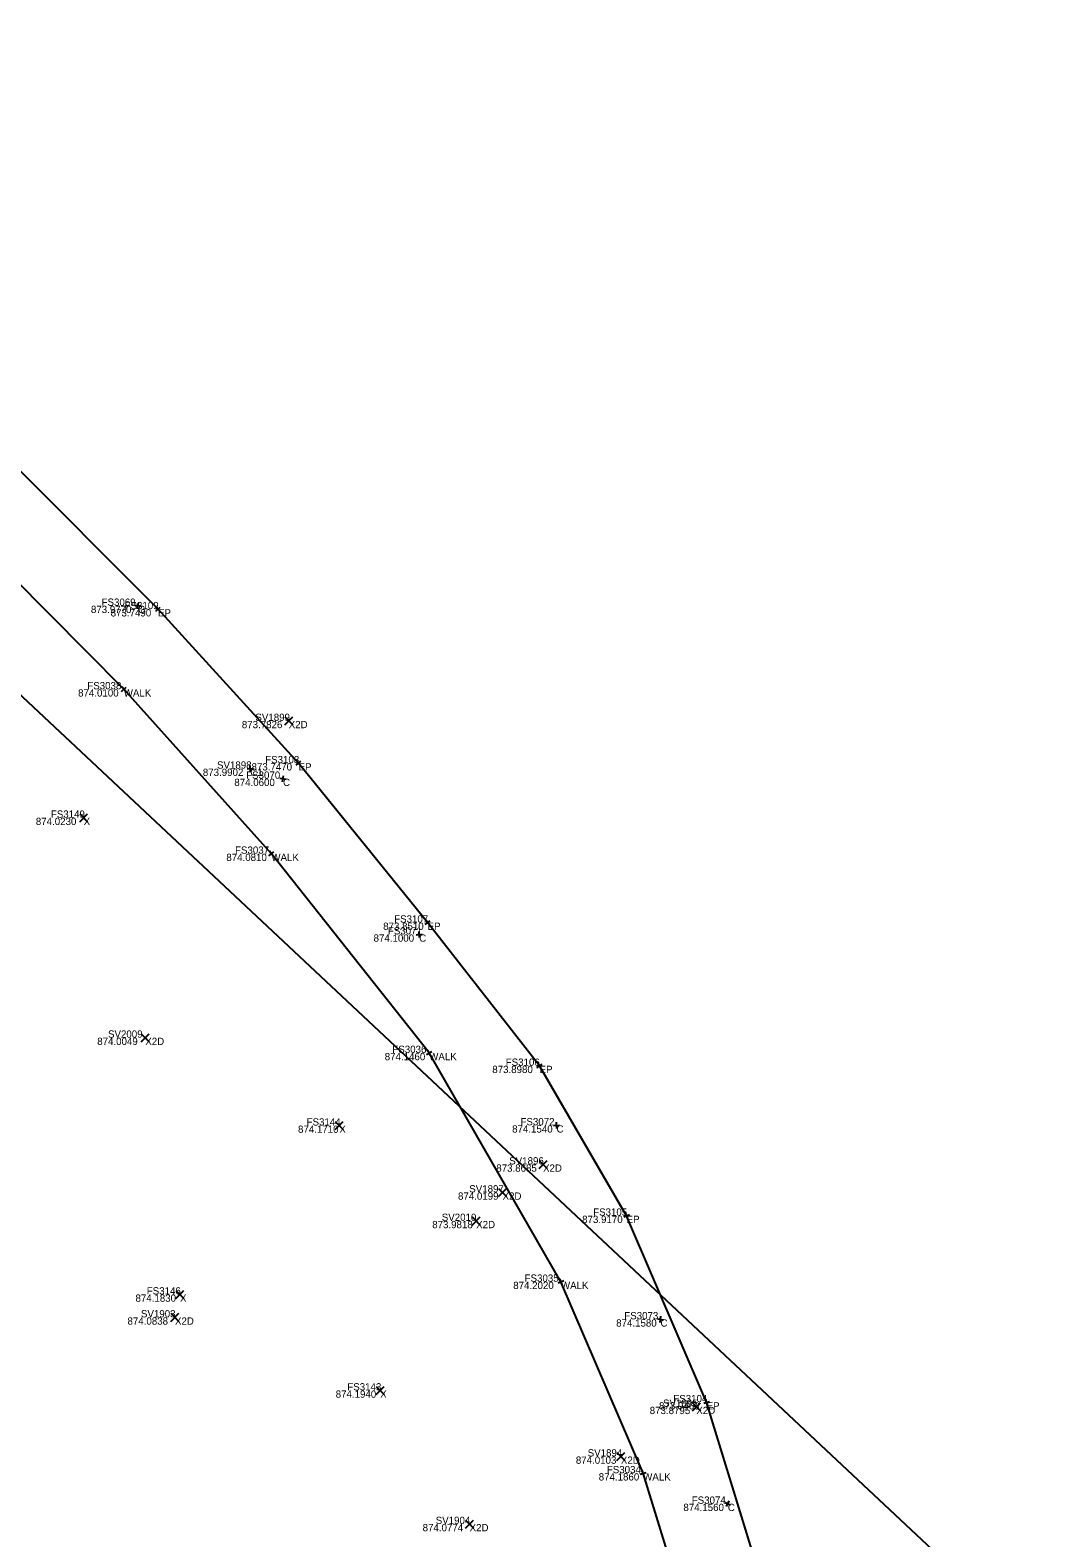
# Model space of a CAD drawing. Extents: x 1479481 to 1575806, y 316056 to 379927.
# Drawn here: x 1480137.43 to 1480145.75, y 379421.16 to 379433.6 of the extents above; entities that cross this region are included whole.
import ezdxf

# ---------------------------------------------------------------- set-up
doc = ezdxf.new("R2010")
doc.units = 0
for name, color, linetype in [('PV_X_Curb', 7, 'Continuous'), ('PV_X_Walk', 7, 'Continuous'), ('SV_X_Random_Point', 7, 'Continuous'), ('SV_X_Shot_Marker', 7, 'Continuous'), ('SV_X_Text_Comment', 7, 'Continuous'), ('SV_X_Text_Elevation', 7, 'Continuous'), ('SV_X_Text_Name', 7, 'Continuous'), ('UT_X_Water', 7, 'Continuous')]:
    doc.layers.add(name, color=color, linetype=linetype)

msp = doc.modelspace()

# ---------------------------------------------------------------- linework, layer by layer
at = {"layer": 'PV_X_Curb'}
for points in [[(1480144.119, 379408.692), (1480144.24, 379410.484), (1480144.247, 379412.184), (1480144.276, 379413.727), (1480144.183, 379415.462), (1480143.996, 379417.344), (1480143.813, 379419.16), (1480143.496, 379420.71), (1480143.015, 379422.278), (1480142.354, 379423.817), (1480141.636, 379425.054), (1480140.711, 379426.236), (1480139.646, 379427.551), (1480138.485, 379428.822), (1480137.236, 379430.074), (1480137.133, 379430.292), (1480135.667, 379431.559), (1480135.19, 379432.332), (1480118.45, 379448.16)], [(1480143.467, 379408.427), (1480143.491, 379410.102), (1480143.626, 379411.891), (1480143.667, 379412.715), (1480143.643, 379414.145), (1480143.592, 379415.709), (1480143.406, 379417.136), (1480143.175, 379418.964), (1480142.832, 379420.583), (1480142.491, 379421.692), (1480141.812, 379423.272), (1480140.724, 379425.16), (1480139.421, 379426.804), (1480138.202, 379428.161), (1480136.669, 379429.706), (1480137.114, 379430.095), (1480136.349, 379430.778), (1480135, 379431.897), (1480118.039, 379447.914)]]:
    msp.add_lwpolyline(points, dxfattribs=at)
at = {"layer": 'PV_X_Walk'}
msp.add_lwpolyline([(1480143.467, 379408.427), (1480143.491, 379410.102), (1480143.626, 379411.891), (1480143.667, 379412.715), (1480143.643, 379414.145), (1480143.592, 379415.709), (1480143.406, 379417.136), (1480143.175, 379418.964), (1480142.832, 379420.583), (1480142.491, 379421.692), (1480141.812, 379423.272), (1480140.724, 379425.16), (1480139.421, 379426.804), (1480138.202, 379428.161), (1480136.669, 379429.706), (1480135.545, 379428.421), (1480134.397, 379429.433)], dxfattribs=at)
at = {"layer": 'SV_X_Random_Point'}
for p, q in [((1480139.531, 379427.867), (1480139.597, 379427.933)), ((1480139.531, 379427.933), (1480139.597, 379427.867)), ((1480137.838, 379427.068), (1480137.904, 379427.134)), ((1480137.838, 379427.134), (1480137.904, 379427.068)), ((1480138.347, 379425.252), (1480138.413, 379425.319)), ((1480138.347, 379425.319), (1480138.413, 379425.252)), ((1480139.949, 379424.528), (1480140.015, 379424.594)), ((1480139.949, 379424.594), (1480140.015, 379424.528)), ((1480141.631, 379424.207), (1480141.697, 379424.273)), ((1480141.631, 379424.273), (1480141.697, 379424.207)), ((1480141.297, 379423.975), (1480141.363, 379424.042)), ((1480141.297, 379424.042), (1480141.363, 379423.975)), ((1480141.079, 379423.74), (1480141.145, 379423.807)), ((1480141.079, 379423.807), (1480141.145, 379423.74)), ((1480138.633, 379423.134), (1480138.699, 379423.2)), ((1480138.633, 379423.2), (1480138.699, 379423.134)), ((1480138.592, 379422.945), (1480138.658, 379423.012)), ((1480138.592, 379423.012), (1480138.658, 379422.945)), ((1480140.286, 379422.342), (1480140.352, 379422.408)), ((1480140.286, 379422.408), (1480140.352, 379422.342)), ((1480142.897, 379422.206), (1480142.963, 379422.273)), ((1480142.897, 379422.273), (1480142.963, 379422.206)), ((1480142.274, 379421.797), (1480142.34, 379421.863)), ((1480142.274, 379421.863), (1480142.34, 379421.797)), ((1480141.025, 379421.239), (1480141.091, 379421.306)), ((1480141.025, 379421.306), (1480141.091, 379421.239))]:
    msp.add_line(p, q, dxfattribs=at)
at = {"layer": 'SV_X_Shot_Marker'}
for p, q in [((1480138.295, 379428.854), (1480138.345, 379428.846)), ((1480138.316, 379428.825), (1480138.324, 379428.875)), ((1480138.32, 379428.85), (1480138.32, 379428.85)), ((1480138.467, 379428.805), (1480138.503, 379428.839)), ((1480138.502, 379428.804), (1480138.468, 379428.84)), ((1480138.485, 379428.822), (1480138.485, 379428.822)), ((1480138.183, 379428.144), (1480138.221, 379428.178)), ((1480138.219, 379428.142), (1480138.185, 379428.18)), ((1480138.202, 379428.161), (1480138.202, 379428.161)), ((1480139.222, 379427.504), (1480139.272, 379427.508)), ((1480139.249, 379427.481), (1480139.245, 379427.531)), ((1480139.247, 379427.506), (1480139.247, 379427.506)), ((1480139.627, 379427.535), (1480139.665, 379427.567)), ((1480139.662, 379427.532), (1480139.63, 379427.57)), ((1480139.646, 379427.551), (1480139.646, 379427.551)), ((1480139.492, 379427.427), (1480139.542, 379427.419)), ((1480139.513, 379427.398), (1480139.521, 379427.448)), ((1480139.517, 379427.423), (1480139.517, 379427.423)), ((1480139.401, 379426.788), (1480139.441, 379426.82)), ((1480139.437, 379426.784), (1480139.405, 379426.824)), ((1480139.421, 379426.804), (1480139.421, 379426.804)), ((1480140.691, 379426.221), (1480140.731, 379426.251)), ((1480140.726, 379426.216), (1480140.696, 379426.256)), ((1480140.711, 379426.236), (1480140.711, 379426.236)), ((1480140.617, 379426.136), (1480140.667, 379426.14)), ((1480140.644, 379426.113), (1480140.64, 379426.163)), ((1480140.642, 379426.138), (1480140.642, 379426.138)), ((1480140.702, 379425.148), (1480140.746, 379425.172)), ((1480140.736, 379425.138), (1480140.712, 379425.182)), ((1480140.724, 379425.16), (1480140.724, 379425.16)), ((1480141.614, 379425.041), (1480141.658, 379425.067)), ((1480141.649, 379425.032), (1480141.623, 379425.076)), ((1480141.636, 379425.054), (1480141.636, 379425.054)), ((1480141.751, 379424.562), (1480141.801, 379424.564)), ((1480141.777, 379424.538), (1480141.775, 379424.588)), ((1480141.776, 379424.563), (1480141.776, 379424.563)), ((1480142.331, 379423.807), (1480142.377, 379423.827)), ((1480142.364, 379423.794), (1480142.344, 379423.84)), ((1480142.354, 379423.817), (1480142.354, 379423.817)), ((1480141.789, 379423.262), (1480141.835, 379423.282)), ((1480141.822, 379423.249), (1480141.802, 379423.295)), ((1480141.812, 379423.272), (1480141.812, 379423.272)), ((1480142.631, 379422.937), (1480142.637, 379422.987)), ((1480142.609, 379422.965), (1480142.659, 379422.959)), ((1480142.634, 379422.962), (1480142.634, 379422.962)), ((1480142.991, 379422.271), (1480143.039, 379422.285)), ((1480143.022, 379422.254), (1480143.008, 379422.302)), ((1480143.015, 379422.278), (1480143.015, 379422.278)), ((1480142.467, 379421.685), (1480142.515, 379421.699)), ((1480142.498, 379421.668), (1480142.484, 379421.716)), ((1480142.491, 379421.692), (1480142.491, 379421.692)), ((1480143.167, 379421.45), (1480143.213, 379421.43)), ((1480143.18, 379421.417), (1480143.2, 379421.463)), ((1480143.19, 379421.44), (1480143.19, 379421.44))]:
    msp.add_line(p, q, dxfattribs=at)
at = {"layer": 'UT_X_Water'}
msp.add_lwpolyline([(1480234.677, 379335.863), (1480225.088, 379345.601), (1480208.322, 379361.342), (1480207.346, 379362.25), (1480199.528, 379369.768), (1480193.21, 379375.651), (1480182.823, 379385.139), (1480177.927, 379389.525), (1480169.423, 379398.321), (1480161.035, 379406.189), (1480144.924, 379421.019), (1480134.739, 379430.559), (1480121.485, 379441.998), (1480113.085, 379450.369), (1480106.418, 379456.915), (1480094.539, 379467.985), (1480089.15, 379472.551), (1480086.751, 379474.713), (1480073.459, 379487.337), (1480068.123, 379493.187), (1480050.678, 379510.207), (1480044.404, 379515.873)], dxfattribs=at)

# ---------------------------------------------------------------- texts
at = {"layer": 'SV_X_Text_Comment'}
for s, p in [('C', (1480138.32, 379428.79)), ('EP', (1480138.485, 379428.762)), ('WALK', (1480138.202, 379428.101)), ('X2D', (1480139.564, 379427.84)), ('C1', (1480139.247, 379427.446)), ('EP', (1480139.646, 379427.491)), ('C', (1480139.517, 379427.363)), ('X', (1480137.871, 379427.041)), ('WALK', (1480139.421, 379426.744)), ('EP', (1480140.711, 379426.176)), ('C', (1480140.642, 379426.078)), ('X2D', (1480138.38, 379425.226)), ('WALK', (1480140.724, 379425.1)), ('EP', (1480141.636, 379424.994)), ('X', (1480139.982, 379424.501)), ('C', (1480141.776, 379424.503)), ('X2D', (1480141.664, 379424.18)), ('X2D', (1480141.33, 379423.949)), ('X2D', (1480141.112, 379423.714)), ('EP', (1480142.354, 379423.757)), ('WALK', (1480141.812, 379423.212)), ('X', (1480138.666, 379423.107)), ('X2D', (1480138.625, 379422.918)), ('C', (1480142.634, 379422.902)), ('X', (1480140.319, 379422.315)), ('X2D', (1480142.93, 379422.18)), ('EP', (1480143.015, 379422.218)), ('X2D', (1480142.307, 379421.77)), ('WALK', (1480142.491, 379421.632)), ('C', (1480143.19, 379421.38)), ('X2D', (1480141.058, 379421.213))]:
    msp.add_text(s, height=0.06, dxfattribs=at).set_placement(p)
at = {"layer": 'SV_X_Text_Elevation'}
for s, p in [('873.9770', (1480137.931, 379428.79)), ('873.7490', (1480138.094, 379428.762)), ('874.0100', (1480137.825, 379428.101)), ('873.7826', (1480139.177, 379427.84)), ('873.9902', (1480138.855, 379427.446)), ('873.7470', (1480139.257, 379427.491)), ('874.0600', (1480139.115, 379427.363)), ('874.0230', (1480137.476, 379427.041)), ('874.0810', (1480139.049, 379426.744)), ('873.8510', (1480140.344, 379426.176)), ('874.1000', (1480140.265, 379426.078)), ('874.0049', (1480137.983, 379425.226)), ('874.1460', (1480140.357, 379425.1)), ('873.8980', (1480141.245, 379424.994)), ('874.1710', (1480139.641, 379424.501)), ('874.1540', (1480141.409, 379424.503)), ('873.8685', (1480141.278, 379424.18)), ('874.0199', (1480140.962, 379423.949)), ('873.9818', (1480140.749, 379423.714)), ('873.9170', (1480141.987, 379423.757)), ('874.2020', (1480141.418, 379423.212)), ('874.1830', (1480138.299, 379423.107)), ('874.0838', (1480138.233, 379422.918)), ('874.1580', (1480142.268, 379422.902)), ('874.1940', (1480139.952, 379422.315)), ('873.8795', (1480142.545, 379422.18)), ('873.9460', (1480142.622, 379422.218)), ('874.0103', (1480141.935, 379421.77)), ('874.1860', (1480142.124, 379421.632)), ('874.1560', (1480142.823, 379421.38)), ('874.0774', (1480140.67, 379421.213))]:
    msp.add_text(s, height=0.06, dxfattribs=at).set_placement(p)
at = {"layer": 'SV_X_Text_Name'}
for s, p in [('FS3069', (1480138.019, 379428.85)), ('FS3109', (1480138.209, 379428.822)), ('FS3038', (1480137.901, 379428.161)), ('SV1899', (1480139.289, 379427.9)), ('FS3108', (1480139.37, 379427.551)), ('SV1898', (1480138.972, 379427.506)), ('FS3070', (1480139.213, 379427.423)), ('FS3149', (1480137.6, 379427.101)), ('FS3037', (1480139.121, 379426.804)), ('FS3107', (1480140.435, 379426.236)), ('FS3071', (1480140.383, 379426.138)), ('SV2009', (1480138.072, 379425.286)), ('FS3036', (1480140.42, 379425.16)), ('FS3106', (1480141.356, 379425.054)), ('FS3144', (1480139.712, 379424.561)), ('FS3072', (1480141.478, 379424.563)), ('SV1896', (1480141.385, 379424.24)), ('SV1897', (1480141.055, 379424.009)), ('FS3105', (1480142.078, 379423.817)), ('SV2010', (1480140.828, 379423.774)), ('FS3035', (1480141.512, 379423.272)), ('FS3146', (1480138.392, 379423.167)), ('SV1903', (1480138.344, 379422.978)), ('FS3073', (1480142.335, 379422.962)), ('FS3143', (1480140.048, 379422.375)), ('SV1895', (1480142.655, 379422.24)), ('FS3104', (1480142.74, 379422.278)), ('SV1894', (1480142.033, 379421.83)), ('FS3034', (1480142.191, 379421.692)), ('FS3074', (1480142.892, 379421.44)), ('SV1904', (1480140.778, 379421.273))]:
    msp.add_text(s, height=0.06, dxfattribs=at).set_placement(p)

doc.saveas('drawing.dxf')
